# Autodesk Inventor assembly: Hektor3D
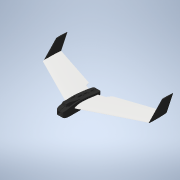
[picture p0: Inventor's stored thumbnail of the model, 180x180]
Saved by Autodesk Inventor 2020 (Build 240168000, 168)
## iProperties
Part Number: Hektor3D
Document SubType Name: Assembly
Designer: Admin
Mass: 21163.6 g
Surface Area: 21673.8 cm^2
Volume: 18590.6 cm^3
Density: 1.1384 g/cm^3
Revision: -
VAULT_Status: in Bearbeitung
Gewicht: 21,164 kg
InventorVersion: 2019.4
Author: Admin
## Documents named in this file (9)
- C:\Users\MartinDJay\Documents\GitHub\CAD_Elements\CAD\Hektor\Hektor_3D\Hektor3D.iam
- HEKTOR3D_HEKTOR3D.IAM
- C:\Users\MartinDJay\Documents\GitHub\CAD_Elements\CAD\Hektor\Hektor_3D\Rumpfhälfte.ipt
- C:\Users\MartinDJay\Documents\GitHub\CAD_Elements\CAD\Hektor\Hektor_3D\Rumpfhälfte1.ipt
- C:\Users\MartinDJay\Documents\GitHub\CAD_Elements\CAD\Hektor\Hektor_3D\wing_r.ipt
- C:\Users\MartinDJay\Documents\GitHub\CAD_Elements\CAD\Hektor\Hektor_3D\Wing_L.ipt
- C:\Users\MartinDJay\Documents\GitHub\CAD_Elements\CAD\Hektor\Hektor_3D\Winlet_R.ipt
- C:\Users\MartinDJay\Documents\GitHub\CAD_Elements\CAD\Hektor\Hektor_3D\Winglet_L.ipt
- C:\Users\MartinDJay\Documents\GitHub\CAD_Elements\CAD\Hektor\Hektor_3D\canopy.ipt
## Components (7 placed, 7 different names)
1. RUMPFHÄLFTE_RUMPFHÄLFTE:1 — Fluchtend:1, Fluchtend:2, Fluchtend:3, Passend:3, Passend:4, Passend:23, Winkel:4
2. RUMPFHÄLFTE1_RUMPFHÄLFTE1:1 — Passend:1, Fluchtend:4, Passend:2, Passend:5, Passend:6, Passend:24, Passend:40
3. WING_R_WING_R:1 — Passend:3, Passend:4, Passend:9, Fluchtend:12, Passend:38, Winkel:4, Passend:39
4. WING_L_WING_L:1 — Passend:5, Passend:6, Passend:12, Passend:38
5. WINLET_R_WINLET_R:1 — Passend:9, Fluchtend:12, Fluchtend:13, Passend:11, Passend:39
6. WINGLET_L_WINGLET_L:1 — Fluchtend:13, Passend:11, Passend:12
7. CANOPY_CANOPY:1 — Passend:23, Passend:24, Fluchtend:15, Passend:40
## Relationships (22: Mate 14, Flush 7, Angle 1)
- Fluchtend:1 [Flush]: RUMPFHÄLFTE_RUMPFHÄLFTE:1
- Fluchtend:2 [Flush]: RUMPFHÄLFTE_RUMPFHÄLFTE:1
- Fluchtend:3 [Flush]: RUMPFHÄLFTE_RUMPFHÄLFTE:1
- Passend:1 [Mate]: RUMPFHÄLFTE1_RUMPFHÄLFTE1:1
- Fluchtend:4 [Flush]: RUMPFHÄLFTE1_RUMPFHÄLFTE1:1
- Passend:2 [Mate]: RUMPFHÄLFTE1_RUMPFHÄLFTE1:1
- Passend:3 [Mate]: RUMPFHÄLFTE_RUMPFHÄLFTE:1 ↔ WING_R_WING_R:1
- Passend:4 [Mate]: RUMPFHÄLFTE_RUMPFHÄLFTE:1 ↔ WING_R_WING_R:1
- Passend:5 [Mate]: RUMPFHÄLFTE1_RUMPFHÄLFTE1:1 ↔ WING_L_WING_L:1
- Passend:6 [Mate]: RUMPFHÄLFTE1_RUMPFHÄLFTE1:1 ↔ WING_L_WING_L:1
- Passend:9 [Mate]: WING_R_WING_R:1 ↔ WINLET_R_WINLET_R:1
- Fluchtend:12 [Flush]: WING_R_WING_R:1 ↔ WINLET_R_WINLET_R:1
- Fluchtend:13 [Flush]: WINLET_R_WINLET_R:1 ↔ WINGLET_L_WINGLET_L:1
- Passend:11 [Mate]: WINLET_R_WINLET_R:1 ↔ WINGLET_L_WINGLET_L:1
- Passend:12 [Mate]: WING_L_WING_L:1 ↔ WINGLET_L_WINGLET_L:1
- Passend:23 [Mate]: RUMPFHÄLFTE_RUMPFHÄLFTE:1 ↔ CANOPY_CANOPY:1
- Passend:24 [Mate]: RUMPFHÄLFTE1_RUMPFHÄLFTE1:1 ↔ CANOPY_CANOPY:1
- Fluchtend:15 [Flush]: CANOPY_CANOPY:1
- Passend:38 [Mate]: WING_R_WING_R:1 ↔ WING_L_WING_L:1
- Winkel:4 [Angle]: RUMPFHÄLFTE_RUMPFHÄLFTE:1 ↔ WING_R_WING_R:1
- Passend:39 [Mate]: WING_R_WING_R:1 ↔ WINLET_R_WINLET_R:1
- Passend:40 [Mate]: RUMPFHÄLFTE1_RUMPFHÄLFTE1:1 ↔ CANOPY_CANOPY:1
## Named parameters: Gewicht = 211.63592 mm
